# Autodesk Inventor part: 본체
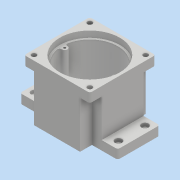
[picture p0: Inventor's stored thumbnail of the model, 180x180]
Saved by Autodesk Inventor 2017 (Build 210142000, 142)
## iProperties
Part Number: 본체
Material: 일반
Document SubType Name: Modeling
Designer: user
Density: 1 g/cm^3
Appearance: 기본값
Author: user
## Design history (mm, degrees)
sketch "스케치1"
  geometry: L1 (0, 0)-(140, 0); L2 (0, 0)-(0, 60); L3 (0, 60)-(140, 60); L4 (140, 60)-(140, 0)
  constraints: 8 end point, 1 horizontal, 1 perpendicular, 1 vertical
  dimensions: "d0" = 140 distance of L1.start L1.end; "d4" = 60 distance of L1.start L2.end; "d5" = 140 distance of L2.end L3.end
extrude "돌출1" new body sketch "스케치1" distance "d6" = 13; taper "d7" = 0 deg
sketch "스케치2"
  geometry: L1 (-140, 60)-(0, 60) reference; L2 (-70, 60)-(-70, 0); L3 (0, 0)-(-140, 0) reference; L4 (-140, 30)-(0, 30); L5 (-117, 77)-(-117, -17); L6 (-23, 77)-(-23, -17); L7 (-117, 77)-(-23, 77); L8 (-117, -17)-(-23, -17)
  constraints: 12 end point, 4 parallel, 2 midpoint, 1 horizontal
  dimensions: "d8" = 47 distance between parallel lines of L2 L5; "d9" = 47 distance between parallel lines of L2 L6; "d10" = 47 distance between parallel lines of L4 L7; "d12" = 47 distance between parallel lines of L4 L8
extrude "돌출2" join sketch "스케치2" distance "d13" = 80; taper "d14" = 0 deg
sketch "스케치4"
  geometry: L1 (0, 0)-(-23, 0) reference; L2 (-23, 0)-(-23, -17); L3 (-37, -17)-(-37, 0); L4 (-37, -17)-(-23, -17); L5 (-103, -17)-(-117, -17); L6 (-117, 0)-(-140, 0) reference; L7 (-117, 0)-(-103, 0); L8 (-103, 0)-(-103, -17); L9 (-23, 0)-(-37, 0); L10 (-117, -17)-(-117, 0) reference; L11 (-117, -17)-(-117, 0); L12 (0, 60)-(0, 0) reference; L13 (0, 30)-(-140, 30); L14 (-140, 0)-(-140, 60) reference; L15 (-23, 60)-(-23, 77); L16 (-37, 77)-(-37, 60); L17 (-37, 77)-(-23, 77); L18 (-23, 60)-(-37, 60); L19 (-103, 77)-(-117, 77); L20 (-117, 60)-(-103, 60); L21 (-103, 60)-(-103, 77); L22 (-117, 77)-(-117, 60); L23 (-117, 77)-(-117, 60)
  constraints: 36 end point, 8 symmetric about line, 3 horizontal, 2 midpoint, 2 vertical, 1 collinear
extrude "돌출3" cut sketch "스케치4" distance "d19" = 67; taper "d20" = 0 deg
sketch "스케치7"
  geometry: L1 (37, -17)-(103, -17) reference; L2 (70, -17)-(70, 97.053); L3 (0, 60)-(0, 0) reference; L4 (0, 30)-(150.591, 30); C1 r 43 at (70, 30)
  constraints: 4 end point, 2 midpoint, 2 point on line, 1 centre point, 1 horizontal, 1 vertical
  dimensions: "d26" = 86 diameter of C1
extrude "돌출4" cut sketch "스케치7" distance "d27" = 9; taper "d28" = 0 deg
sketch "스케치8"
  geometry: C1 r 40 at (0, 0); 1 further point
  constraints: 1 centre point
  dimensions: "d29" = 80 diameter of C1
sketch "스케치9"
  geometry: L1 (-117, 77)-(-23, 77) reference; L2 (-70, 77)-(-70, -17); L3 (-23, -17)-(-117, -17) reference; L4 (-140, 0)-(-140, 60) reference; L5 (-140, 30)-(0, 30); L6 (0, 60)-(0, 0) reference; L7 (-70, 30)-(-71, 30); L8 (-70, 30)-(-70, 41); L9 (-70, 30)-(-70, 10); C1 r 27.5 at (-70, 41)
  constraints: 10 end point, 5 midpoint, 3 point on line, 1 centre point, 1 coincident
  dimensions: "d30" = 1 distance of L7.start L7.end; "d31" = 11 distance of L7.start L8.end; "d32" = 20 distance of L7.start L9.end; "d35" = 55 diameter of C1
extrude "돌출5" join sketch "스케치9" distance "d36" = 7; taper "d37" = 0 deg
sketch "스케치10"
  geometry: L1 (-33, 36)-(33, 36) reference; C1 r 27.5 at (0, 0) reference; C2 r 16 at (0, 0); 1 further point
  constraints: 1 centre point, 1 coincident
  dimensions: "d39" = 32 diameter of C2
extrude "돌출6" cut sketch "스케치10" distance "d40" = 8.3; taper "d41" = 0 deg
sketch "스케치11"
  geometry: C1 r 12.5 at (0, 0); 1 further point
  constraints: 1 centre point
  dimensions: "d44" = 25 diameter of C1
extrude "돌출7" cut sketch "스케치11" distance "d45" = 4.7; taper "d46" = 0 deg
sketch "스케치12"
  geometry: C1 r 17.5 at (0, 0); 1 further point
  constraints: 1 centre point
  dimensions: "d47" = 35 diameter of C1
extrude "돌출8" cut sketch "스케치12" distance "d48" = 10; taper "d49" = 0 deg
extrude "돌출9" cut sketch "스케치8" distance "d50" = 62; taper "d51" = 0 deg
node "작업 평면2"
sketch "스케치18"
  geometry: A1 r 40 centre (0, 0) between (-39.279, 7.559) and (-39.279, -7.559) reference; A2 r 4 centre (-36, 0) between (-36.19, -3.995) and (-36.19, 3.995); A3 r 3 centre (-36.333, 6.992) between (-39.279, 7.559) and (-36.19, 3.995); A4 r 3 centre (-36.333, -6.992) between (-36.19, -3.995) and (-39.279, -7.559); A5 r 40 centre (0, 0) between (-39.279, 7.559) and (-39.279, -7.559); 1 further point
  constraints: 10 point on circle, 6 tangent, 4 centre point, 1 horizontal alignment
  dimensions: "d81" = 8 diameter of A2; "d82" = 36 distance of A1.centre A2.centre; "d83" = 3 radius of A3; "d84" = 3 radius of A4
extrude "돌출12" join sketch "스케치18" stored distance "d85" = 7; taper "d86" = 0 deg
sketch "스케치20"
  geometry: L1 (-32, 0)-(-36, 0); A1 r 4 centre (-36, 0) between (-36.19, -3.995) and (-36.19, 3.995) reference; 1 further point
  constraints: 2 end point, 1 horizontal, 1 point on circle
hole "구멍1" sketch "스케치20" at (-36, 0) diameter "d87" = 3.242; stored, may be unused: countersink angle "d91" = 90 deg, drill point angle "d93" = 118 deg; dims "d88" = 7, "d89" = 4, "d90" = 2, "d92" = 9
node "작업 평면1"
chamfer "모따기1" distance "d94" = 0.8; stored, may be unused: second distance "d95" = 2, angle "d96" = 30 deg
sketch "스케치21"
  geometry: C1 r 21 at (0, 11); C2 r 15 at (0, -20); C3 r 17.5 at (0, 11) reference; 1 further point
  constraints: 2 centre point, 1 concentric, 1 vertical alignment
  dimensions: "d97" = 42 diameter of C1; "d98" = 30 diameter of C2; "d101" = 31 distance of C1.centre C2.centre
extrude "돌출13" join sketch "스케치21" distance "d99" = 7; taper "d100" = 0 deg
hole "구멍2" diameter "d104" = 35; stored, may be unused: countersink angle "d108" = 90 deg, drill point angle "d110" = 0 deg; dims "d102" = 10, "d103" = 10, "d105" = 7, "d106" = 4, "d107" = 2, "d109" = 10
hole "구멍3" diameter "d113" = 19; stored, may be unused: countersink angle "d117" = 90 deg, drill point angle "d119" = 0 deg; dims "d111" = 10, "d112" = 10, "d114" = 7, "d115" = 22, "d116" = 7, "d118" = 10
fillet "모깎기1" dims "d120" = 3
chamfer "모따기2" distance "d121" = 1; stored, may be unused: second distance "d122" = 2, angle "d123" = 30 deg
sketch "스케치22"
  geometry: L1 (-117, 77)-(-23, 77) reference; L2 (-70, 77)-(-30, 77); L3 (-23, 77)-(-23, -17) reference; L4 (-23, 30)-(-23, 70); L5 (-23, 70)-(-44.083, 70); L6 (-30, 77)-(-30, 52.8); L7 (-23, 30)-(-140, 30); L8 (-140, 0)-(-140, 60) reference; L9 (-70, 77)-(-70, -17); C1 r 3.5 at (-30, 70); C2 r 3.5 at (-30, -10); C3 r 3.5 at (-110, 70); C4 r 3.5 at (-110, -10); 1 further point
  constraints: 12 end point, 4 centre point, 3 midpoint, 3 point on line, 3 symmetric about line, 2 perpendicular, 2 vertical, 3 other
  dimensions: "d124" = 40 distance of L2.start L2.end; "d125" = 40 distance of L4.start L4.end; "d126" = 7 diameter of C1
extrude "돌출14" cut sketch "스케치22" distance "d127" = 50; taper "d128" = 0 deg
fillet "모깎기2" dims "d129" = 3
sketch "스케치23"
  geometry: L1 (0, 57)-(0, 3) reference; L2 (0, 30)-(0, 49); L3 (0, 49)-(0, 11); L4 (-114, 77)-(-26, 77) reference; L5 (-70, 77)-(-10, 77); L6 (-10, 77)-(-10, -14.148); L7 (0, 49)-(-159.364, 49); L8 (0, 11)-(-172.726, 11); L9 (-70, 77)-(-130, 77); L10 (-130, 77)-(-130, -21.222); C1 r 2.25 at (-130, 49); C2 r 2.25 at (-130, 11); C3 r 2.25 at (-10, 11); C4 r 2.25 at (-10, 49); 1 further point
  constraints: 16 end point, 11 point on line, 4 centre point, 2 horizontal, 2 midpoint, 1 collinear, 1 perpendicular, 1 vertical
  dimensions: "d130" = 19 distance of L2.start L2.end; "d131" = 38 distance of L2.end L3.end; "d132" = 60 distance of L5.start L5.end; "d133" = 60 distance of L5.start L9.end; "d134" = 4.5 diameter of C1; "d135" = 4.5 diameter of C2; "d136" = 4.5 diameter of C3; "d137" = 4.5 diameter of C4
extrude "돌출15" cut sketch "스케치23" distance "d138" = 50; taper "d139" = 0 deg
sketch "스케치24"
  geometry: C1 r 2.25 at (10, 49) reference; C2 r 5 at (10, 49); C3 r 2.25 at (10, 11) reference; C4 r 5 at (10, 11); C5 r 5 at (129.989, 49); C6 r 2.25 at (130, 11) reference; C7 r 5 at (130, 11); 1 further point
  constraints: 4 centre point, 3 coincident
  dimensions: "d140" = 10 diameter of C2; "d141" = 10 diameter of C4; "d142" = 10 diameter of C5; "d143" = 10 diameter of C7
extrude "돌출16" cut sketch "스케치24" distance "d144" = 5; taper "d145" = 0 deg
sketch "스케치25"
  geometry: L1 (77, -80)-(-11, -80) reference; L2 (60.5, 7)-(5.5, 7) reference; 2 further points
  constraints: 1 other
  dimensions: "d146" = 40 distance from line of point (33.965, -40) L1
feature "엠보싱1" sketch "스케치25" dims "d0" = 140, "d4" = 60, "d5" = 140, "d147" = 0.5, "d148" = 0
node "솔리드1"
mirror "미러1"
